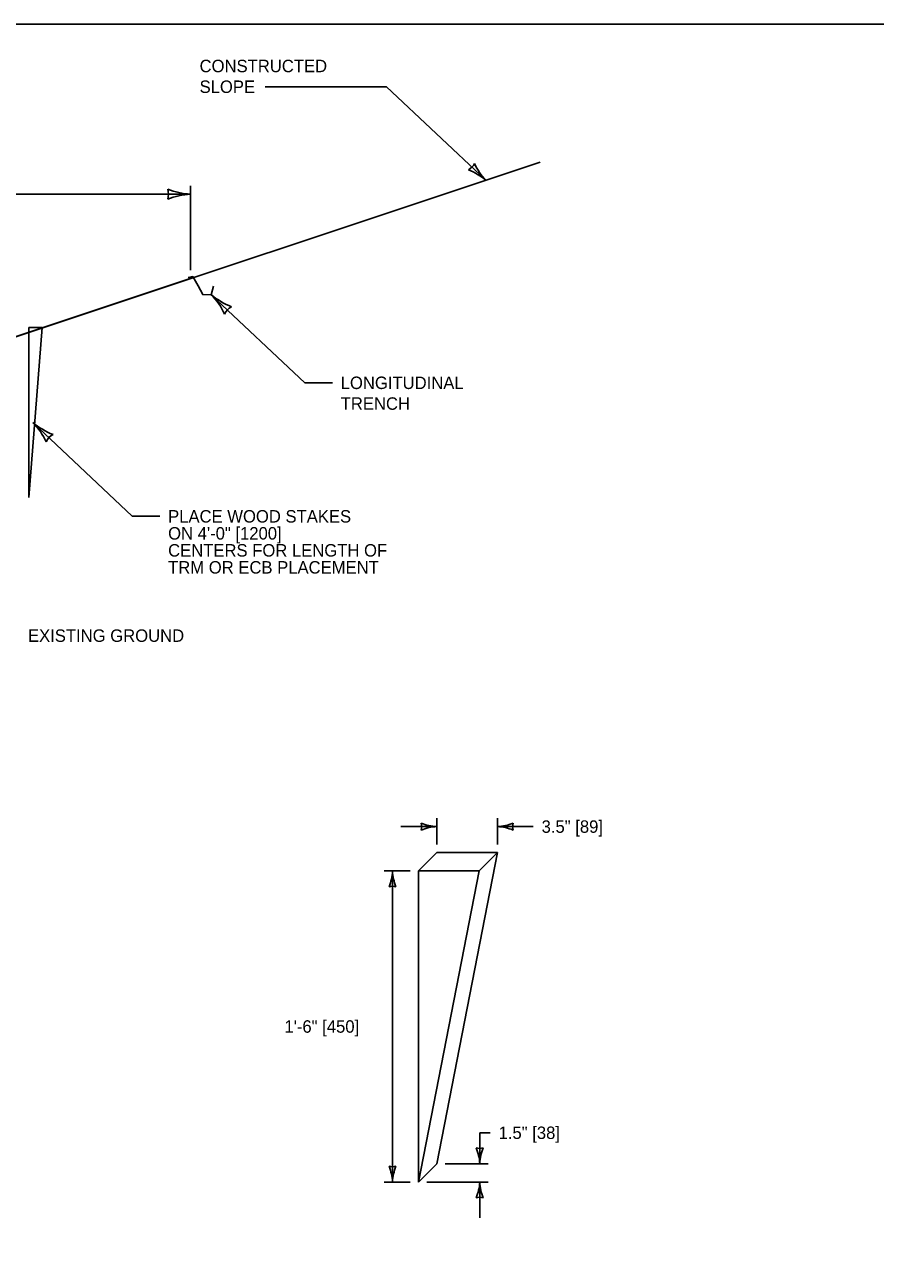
# Model space of a CAD drawing. Extents: x 49977.1 to 50021, y 49987.6 to 50011.4.
# Drawn here: x 50006.16 to 50010.27, y 49993.14 to 49999 of the extents above; entities that cross this region are included whole.
import ezdxf

# ---------------------------------------------------------------- set-up
doc = ezdxf.new("R2010")
doc.units = 0
for name, color, linetype in [('Level 1', 7, 'Continuous'), ('Level 2', 7, 'Continuous'), ('Level 3', 7, 'Continuous')]:
    doc.layers.add(name, color=color, linetype=linetype)

msp = doc.modelspace()

# ---------------------------------------------------------------- linework, layer by layer
at = {"layer": 'Level 1'}
for p, q in [((50008.6533, 49998.3342), (50004.4319, 49996.929)), ((50006.2507, 49997.537), (50006.1872, 49996.7173)), ((50006.1872, 49997.537), (50006.1872, 49996.7173)), ((50006.1872, 49997.537), (50006.2507, 49997.537)), ((50008.0668, 49994.9159), (50008.1552, 49995.0043)), ((50008.4469, 49995.0043), (50008.1552, 49993.5043)), ((50008.1552, 49995.0043), (50008.4469, 49995.0043)), ((50008.3585, 49994.9159), (50008.4469, 49995.0043)), ((50008.0668, 49994.9159), (50008.0668, 49993.4159)), ((50008.3585, 49994.9159), (50008.0668, 49993.4159)), ((50008.0668, 49994.9159), (50008.3585, 49994.9159)), ((50008.1552, 49993.5043), (50008.0668, 49993.4159))]:
    msp.add_line(p, q, dxfattribs=at)
msp.add_lwpolyline([(49999.3835, 49998.9992), (50016.7501, 49998.9992), (50016.7501, 49987.7988), (49999.3835, 49987.7988)], close=True, dxfattribs=at)
for points in [[(50006.97, 49997.775), (50004.4319, 49996.929), (50004.1717, 49996.9836), (50003.8436, 49997.0913), (50003.7305, 49997.1179), (50003.4964, 49997.1888), (50002.85, 49997.3379), (50002.6023, 49997.4026), (50001.8939, 49997.5493)], [(50007.0781, 49997.7369), (50007.067, 49997.6951), (50007.0254, 49997.6954), (50007.0043, 49997.738), (50006.9774, 49997.7829), (50006.9553, 49997.7783)]]:
    msp.add_lwpolyline(points, dxfattribs=at)
at = {"layer": 'Level 3'}
for p, q in [((50007.3274, 49998.6982), (50007.9126, 49998.6982)), ((50008.3914, 49998.247), (50007.9126, 49998.6982)), ((50006.967, 49997.814), (50006.967, 49998.2199)), ((50001.8939, 49998.1799), (50006.967, 49998.1799)), ((50007.0669, 49997.6949), (50007.5177, 49997.2702)), ((50007.6512, 49997.2702), (50007.5177, 49997.2702)), ((50006.2065, 49997.0789), (50006.6853, 49996.6278)), ((50006.8187, 49996.6278), (50006.6853, 49996.6278)), ((50008.1552, 49995.0443), (50008.1552, 49995.17)), ((50008.4469, 49995.0443), (50008.4469, 49995.17)), ((50007.9817, 49995.13), (50008.1552, 49995.13)), ((50008.4469, 49995.13), (50008.6203, 49995.13)), ((50008.0268, 49994.9159), (50007.9011, 49994.9159)), ((50007.9411, 49993.4159), (50007.9411, 49994.9159)), ((50008.3618, 49993.6534), (50008.4128, 49993.6534)), ((50008.3618, 49993.5043), (50008.3618, 49993.6534)), ((50008.1952, 49993.5043), (50008.4018, 49993.5043)), ((50008.0268, 49993.4159), (50007.9011, 49993.4159)), ((50008.1068, 49993.4159), (50008.4018, 49993.4159)), ((50008.3618, 49993.2424), (50008.3618, 49993.4159))]:
    msp.add_line(p, q, dxfattribs=at)
for centre, radius, start, end in [((50008.2743, 49998.3574), 0.0687, 298.84282, 334.56518), ((50008.5909, 49998.442), 0.279, 204.16001, 224.34352), ((50008.2016, 49998.0246), 0.2924, 49.53131, 68.78116), ((50006.9803, 49998.5021), 0.3224, 247.45601, 267.63952), ((50006.781, 49998.1799), 0.0794, 342.13882, 17.86118), ((50006.9836, 49997.8424), 0.3379, 92.82731, 112.07716), ((50006.8364, 49997.4698), 0.3224, 24.16001, 44.34352), ((50007.2863, 49997.9522), 0.3379, 229.53131, 248.78116), ((50007.2023, 49997.5676), 0.0794, 118.84282, 154.56518), ((50005.9759, 49996.8535), 0.3224, 24.16001, 44.34352), ((50006.4258, 49997.336), 0.3379, 229.53131, 248.78116), ((50006.3418, 49996.9514), 0.0794, 118.84282, 154.56518), ((50008.1643, 49995.3521), 0.2223, 247.45601, 267.63952), ((50008.027, 49995.13), 0.0548, 342.13882, 17.86118), ((50008.1667, 49994.8973), 0.233, 92.82731, 112.07716), ((50008.4354, 49995.3627), 0.233, 272.82731, 292.07716), ((50008.4377, 49994.9079), 0.2223, 67.45601, 87.63952), ((50008.5751, 49995.13), 0.0548, 162.13882, 197.86118), ((50007.7189, 49994.925), 0.2223, 337.45601, 357.63952), ((50008.1738, 49994.9274), 0.233, 182.82731, 202.07716), ((50007.9411, 49994.7877), 0.0548, 72.13882, 107.86118), ((50008.3618, 49993.6325), 0.0548, 252.13882, 287.86118), ((50008.129, 49993.4928), 0.233, 2.82731, 22.07716), ((50008.5839, 49993.4951), 0.2223, 157.45601, 177.63952), ((50007.9411, 49993.5441), 0.0548, 252.13882, 287.86118), ((50007.7083, 49993.4044), 0.233, 2.82731, 22.07716), ((50008.1632, 49993.4067), 0.2223, 157.45601, 177.63952), ((50008.1396, 49993.425), 0.2223, 337.45601, 357.63952), ((50008.5945, 49993.4274), 0.233, 182.82731, 202.07716), ((50008.3618, 49993.2877), 0.0548, 72.13882, 107.86118)]:
    msp.add_arc(centre, radius, start, end, dxfattribs=at)

# ---------------------------------------------------------------- texts
at = {"layer": 'Level 2'}
for s, p in [('CONSTRUCTED', (50007.0105, 49998.7682)), ('SLOPE', (50007.0105, 49998.6682)), ('LONGITUDINAL ', (50007.6912, 49997.2402)), ('TRENCH', (50007.6912, 49997.1402)), ('PLACE WOOD STAKES', (50006.8587, 49996.5963)), ('ON 4\'-0" [1200] ', (50006.8587, 49996.5143)), ('CENTERS FOR LENGTH OF', (50006.8587, 49996.4323)), ('TRM OR ECB PLACEMENT', (50006.8587, 49996.3503)), ('EXISTING GROUND', (50006.1827, 49996.0209)), ('3.5" [89]', (50008.6603, 49995.1)), ('1\'-6" [450]', (50007.4198, 49994.1359)), ('1.5" [38]', (50008.4528, 49993.6234))]:
    msp.add_text(s, height=0.06, dxfattribs=at).set_placement(p)

doc.saveas('drawing.dxf')
